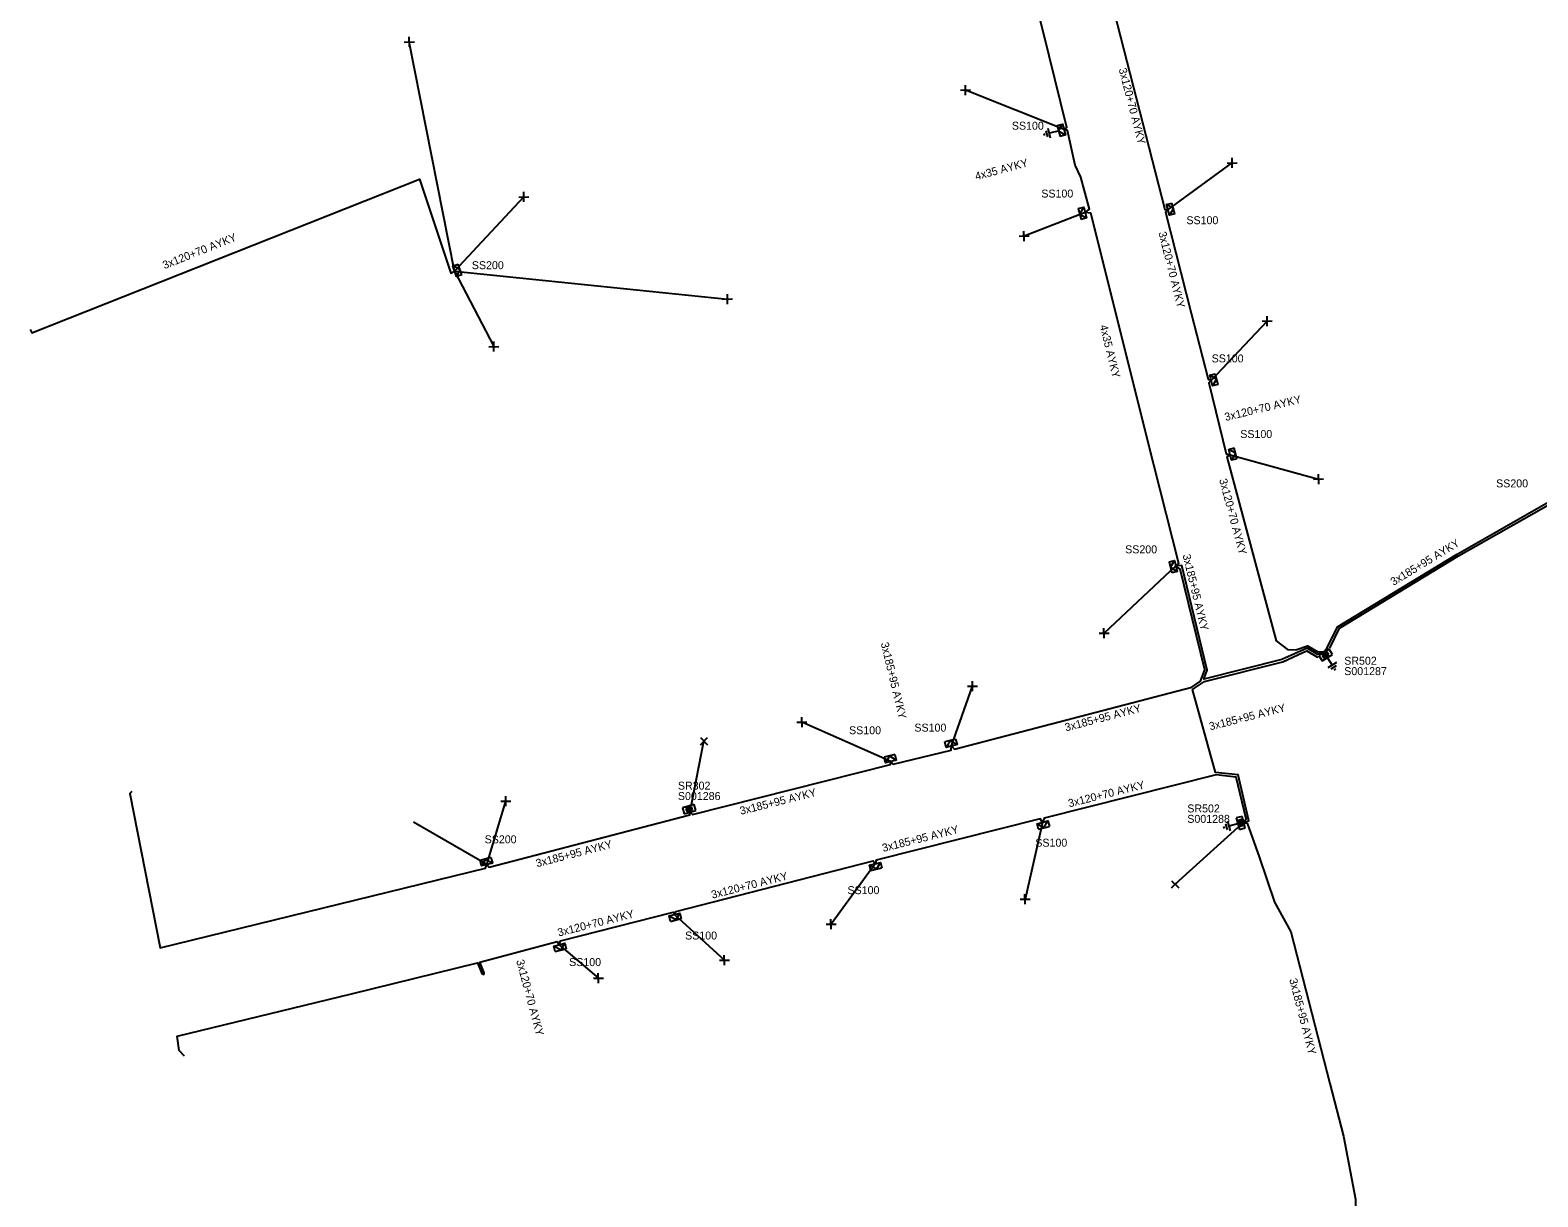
# Model space of a CAD drawing. Extents: x -762500 to -761285, y -1155006 to -1154135.
# Drawn here: x -762396.1 to -762207.7, y -1154854.2 to -1154708.4 of the extents above; entities that cross this region are included whole.
import ezdxf

# ---------------------------------------------------------------- set-up
doc = ezdxf.new("R2010")
doc.units = 0
for name, color, linetype in [('Vrstva 15', 7, 'Continuous'), ('Vrstva 28', 7, 'Continuous'), ('Vrstva 29', 7, 'Continuous'), ('Vrstva 30', 7, 'Continuous'), ('Vrstva 31', 7, 'Continuous'), ('Vrstva 33', 7, 'Continuous'), ('Vrstva 34', 7, 'Continuous'), ('Vrstva 5', 7, 'Continuous'), ('Vrstva 59', 7, 'Continuous'), ('Vrstva 6', 7, 'Continuous')]:
    doc.layers.add(name, color=color, linetype=linetype)

msp = doc.modelspace()

# ---------------------------------------------------------------- linework, layer by layer
at = {"layer": 'Vrstva 15'}
for points in [[(-762269.379, -1154721.432), (-762269.41, -1154721.308)], [(-762269.347, -1154721.561), (-762269.379, -1154721.432)], [(-762268.981, -1154721.729), (-762269.171, -1154720.965)], [(-762268.622, -1154721.888), (-762268.924, -1154720.675)], [(-762267.56, -1154720.979), (-762268.773, -1154721.281)], [(-762234.107, -1154786.711), (-762233.445, -1154787.771)], [(-762232.915, -1154787.44), (-762233.975, -1154788.102)], [(-762232.955, -1154787.83), (-762233.623, -1154788.248)], [(-762233.114, -1154788.301), (-762233.222, -1154788.369)], [(-762233.001, -1154788.23), (-762233.114, -1154788.301)], [(-762246.928, -1154808.035), (-762246.961, -1154807.911)], [(-762246.893, -1154808.163), (-762246.928, -1154808.035)], [(-762246.524, -1154808.324), (-762246.728, -1154807.564)], [(-762246.162, -1154808.477), (-762246.486, -1154807.27)], [(-762245.117, -1154807.55), (-762246.324, -1154807.873)]]:
    msp.add_lwpolyline(points, dxfattribs=at)
at = {"layer": 'Vrstva 28'}
for points in [[(-762233.814, -1154785.768), (-762235.086, -1154786.563)], [(-762234.043, -1154786.127), (-762234.674, -1154786.521)], [(-762234.058, -1154786.192), (-762234.608, -1154786.536)], [(-762234.073, -1154786.257), (-762234.543, -1154786.551)], [(-762234.088, -1154786.322), (-762234.478, -1154786.566)], [(-762234.038, -1154786.402), (-762234.088, -1154786.322)], [(-762233.972, -1154786.417), (-762234.073, -1154786.257)], [(-762233.907, -1154786.432), (-762234.058, -1154786.192)], [(-762233.842, -1154786.447), (-762234.043, -1154786.127)], [(-762233.417, -1154786.404), (-762233.814, -1154785.768)], [(-762235.086, -1154786.563), (-762234.689, -1154787.199)], [(-762234.689, -1154787.199), (-762233.417, -1154786.404)], [(-762234.674, -1154786.521), (-762234.473, -1154786.842)], [(-762234.608, -1154786.536), (-762234.458, -1154786.777)], [(-762234.543, -1154786.551), (-762234.443, -1154786.711)], [(-762234.478, -1154786.566), (-762234.428, -1154786.646)], [(-762234.473, -1154786.842), (-762233.842, -1154786.447)], [(-762234.458, -1154786.777), (-762233.907, -1154786.432)], [(-762234.443, -1154786.711), (-762233.972, -1154786.417)], [(-762234.428, -1154786.646), (-762234.038, -1154786.402)], [(-762234.418, -1154786.584), (-762234.098, -1154786.384)], [(-762313.167, -1154805.186), (-762314.608, -1154805.599)], [(-762314.608, -1154805.599), (-762314.402, -1154806.32)], [(-762314.402, -1154806.32), (-762312.96, -1154805.907)], [(-762313.472, -1154805.47), (-762314.187, -1154805.675)], [(-762314.187, -1154805.675), (-762314.083, -1154806.038)], [(-762313.505, -1154805.528), (-762314.129, -1154805.707)], [(-762314.129, -1154805.707), (-762314.051, -1154805.98)], [(-762314.083, -1154806.038), (-762313.368, -1154805.833)], [(-762313.537, -1154805.587), (-762314.071, -1154805.74)], [(-762314.071, -1154805.74), (-762314.018, -1154805.922)], [(-762314.051, -1154805.98), (-762313.426, -1154805.801)], [(-762314.018, -1154805.922), (-762313.485, -1154805.768)], [(-762313.569, -1154805.645), (-762314.012, -1154805.772)], [(-762314.012, -1154805.772), (-762313.986, -1154805.863)], [(-762313.986, -1154805.863), (-762313.543, -1154805.736)], [(-762313.596, -1154805.702), (-762313.959, -1154805.806)], [(-762313.543, -1154805.736), (-762313.569, -1154805.645)], [(-762313.485, -1154805.768), (-762313.537, -1154805.587)], [(-762313.426, -1154805.801), (-762313.505, -1154805.528)], [(-762313.368, -1154805.833), (-762313.472, -1154805.47)], [(-762312.96, -1154805.907), (-762313.167, -1154805.186)], [(-762244.69, -1154806.657), (-762245.415, -1154806.851)], [(-762245.415, -1154806.851), (-762245.026, -1154808.3)], [(-762244.302, -1154808.105), (-762244.69, -1154806.657)], [(-762244.771, -1154807.063), (-762245.136, -1154807.161)], [(-762245.136, -1154807.161), (-762244.943, -1154807.88)], [(-762244.804, -1154807.121), (-762245.078, -1154807.195)], [(-762245.078, -1154807.195), (-762244.91, -1154807.822)], [(-762245.026, -1154808.3), (-762244.302, -1154808.105)], [(-762244.838, -1154807.179), (-762245.02, -1154807.228)], [(-762245.02, -1154807.228), (-762244.876, -1154807.764)], [(-762244.871, -1154807.237), (-762244.962, -1154807.261)], [(-762244.962, -1154807.261), (-762244.843, -1154807.706)], [(-762244.943, -1154807.88), (-762244.578, -1154807.782)], [(-762244.91, -1154807.822), (-762244.636, -1154807.749)], [(-762244.906, -1154807.289), (-762244.808, -1154807.654)], [(-762244.876, -1154807.764), (-762244.694, -1154807.715)], [(-762244.752, -1154807.682), (-762244.871, -1154807.237)], [(-762244.843, -1154807.706), (-762244.752, -1154807.682)], [(-762244.694, -1154807.715), (-762244.838, -1154807.179)], [(-762244.636, -1154807.749), (-762244.804, -1154807.121)], [(-762244.578, -1154807.782), (-762244.771, -1154807.063)]]:
    msp.add_lwpolyline(points, dxfattribs=at)
at = {"layer": 'Vrstva 31'}
for points in [[(-762267.798, -1154720.323), (-762267.122, -1154720.142), (-762266.76, -1154721.494), (-762267.436, -1154721.675)], [(-762267.798, -1154720.323), (-762267.436, -1154721.675)], [(-762267.617, -1154720.999), (-762267.122, -1154720.142)], [(-762267.617, -1154720.999), (-762266.76, -1154721.494)], [(-762265.159, -1154730.702), (-762264.483, -1154730.521), (-762264.12, -1154731.873), (-762264.797, -1154732.055)], [(-762265.159, -1154730.702), (-762264.797, -1154732.055)], [(-762264.978, -1154731.379), (-762264.483, -1154730.521)], [(-762264.978, -1154731.379), (-762264.12, -1154731.873)], [(-762253.101, -1154731.358), (-762253.777, -1154731.539), (-762254.14, -1154730.186), (-762253.463, -1154730.005)], [(-762253.282, -1154730.681), (-762254.14, -1154730.186)], [(-762253.282, -1154730.681), (-762253.777, -1154731.539)], [(-762253.101, -1154731.358), (-762253.463, -1154730.005)], [(-762342.199, -1154738.957), (-762342.861, -1154739.185), (-762343.317, -1154737.861), (-762342.655, -1154737.633)], [(-762342.427, -1154738.295), (-762343.317, -1154737.861)], [(-762342.427, -1154738.295), (-762342.861, -1154739.185)], [(-762342.199, -1154738.957), (-762342.655, -1154737.633)], [(-762247.702, -1154752.687), (-762248.378, -1154752.868), (-762248.74, -1154751.516), (-762248.064, -1154751.335)], [(-762247.883, -1154752.011), (-762248.74, -1154751.516)], [(-762247.883, -1154752.011), (-762248.378, -1154752.868)], [(-762247.702, -1154752.687), (-762248.064, -1154751.335)], [(-762245.332, -1154761.957), (-762246.008, -1154762.138), (-762246.37, -1154760.786), (-762245.694, -1154760.605)], [(-762245.513, -1154761.281), (-762246.37, -1154760.786)], [(-762245.513, -1154761.281), (-762246.008, -1154762.138)], [(-762245.332, -1154761.957), (-762245.694, -1154760.605)], [(-762253.81, -1154774.847), (-762253.131, -1154774.678), (-762252.792, -1154776.037), (-762253.471, -1154776.206)], [(-762253.81, -1154774.847), (-762253.471, -1154776.206)], [(-762253.641, -1154775.527), (-762253.131, -1154774.678)], [(-762253.641, -1154775.527), (-762252.792, -1154776.037)], [(-762280.492, -1154796.992), (-762281.845, -1154797.354)], [(-762280.492, -1154796.992), (-762280.311, -1154797.668), (-762281.664, -1154798.03), (-762281.845, -1154797.354)], [(-762281.169, -1154797.173), (-762281.664, -1154798.03)], [(-762281.169, -1154797.173), (-762280.311, -1154797.668)], [(-762288.067, -1154798.93), (-762289.426, -1154799.269)], [(-762288.067, -1154798.93), (-762287.898, -1154799.609), (-762289.256, -1154799.948), (-762289.426, -1154799.269)], [(-762288.746, -1154799.099), (-762289.256, -1154799.948)], [(-762288.746, -1154799.099), (-762287.898, -1154799.609)], [(-762270.127, -1154808.268), (-762270.309, -1154807.592), (-762268.956, -1154807.23), (-762268.775, -1154807.906)], [(-762269.451, -1154808.087), (-762270.309, -1154807.592)], [(-762270.127, -1154808.268), (-762268.775, -1154807.906)], [(-762269.451, -1154808.087), (-762268.956, -1154807.23)], [(-762338.552, -1154811.811), (-762339.904, -1154812.174)], [(-762338.552, -1154811.811), (-762338.371, -1154812.488), (-762339.723, -1154812.85), (-762339.904, -1154812.174)], [(-762339.228, -1154811.993), (-762339.723, -1154812.85)], [(-762339.228, -1154811.993), (-762338.371, -1154812.488)], [(-762291.063, -1154813.42), (-762291.232, -1154812.741), (-762289.874, -1154812.402), (-762289.705, -1154813.081)], [(-762290.384, -1154813.251), (-762289.874, -1154812.402)], [(-762290.384, -1154813.251), (-762291.232, -1154812.741)], [(-762291.063, -1154813.42), (-762289.705, -1154813.081)], [(-762316.118, -1154819.778), (-762316.299, -1154819.102), (-762314.947, -1154818.74), (-762314.766, -1154819.416)], [(-762315.442, -1154819.597), (-762316.299, -1154819.102)], [(-762316.118, -1154819.778), (-762314.766, -1154819.416)], [(-762315.442, -1154819.597), (-762314.947, -1154818.74)], [(-762330.507, -1154823.548), (-762330.689, -1154822.872), (-762329.336, -1154822.51), (-762329.155, -1154823.186)], [(-762329.831, -1154823.367), (-762330.689, -1154822.872)], [(-762330.507, -1154823.548), (-762329.155, -1154823.186)], [(-762329.831, -1154823.367), (-762329.336, -1154822.51)]]:
    msp.add_lwpolyline(points, dxfattribs=at)
at = {"layer": 'Vrstva 34'}
for points in [[(-762349.375, -1154709.891), (-762348.125, -1154709.869)], [(-762348.739, -1154710.505), (-762348.761, -1154709.255)], [(-762279.875, -1154715.891), (-762278.625, -1154715.869)], [(-762279.239, -1154716.505), (-762279.261, -1154715.255)], [(-762246.565, -1154725.011), (-762245.315, -1154724.989)], [(-762245.929, -1154725.625), (-762245.951, -1154724.375)], [(-762335.065, -1154729.261), (-762333.815, -1154729.239)], [(-762334.429, -1154729.875), (-762334.451, -1154728.625)], [(-762271.929, -1154734.755), (-762271.951, -1154733.505)], [(-762272.565, -1154734.141), (-762271.315, -1154734.119)], [(-762309.625, -1154742.011), (-762308.375, -1154741.989)], [(-762308.989, -1154742.625), (-762309.011, -1154741.375)], [(-762242.185, -1154744.761), (-762240.935, -1154744.739)], [(-762241.549, -1154745.375), (-762241.571, -1154744.125)], [(-762338.825, -1154747.961), (-762337.575, -1154747.939)], [(-762338.189, -1154748.575), (-762338.211, -1154747.325)], [(-762235.755, -1154764.511), (-762234.505, -1154764.489)], [(-762235.119, -1154765.125), (-762235.141, -1154763.875)], [(-762262.565, -1154783.761), (-762261.315, -1154783.739)], [(-762261.929, -1154784.375), (-762261.951, -1154783.125)], [(-762278.369, -1154791.005), (-762278.391, -1154789.755)], [(-762279.005, -1154790.391), (-762277.755, -1154790.369)], [(-762300.315, -1154794.891), (-762299.065, -1154794.869)], [(-762299.679, -1154795.505), (-762299.701, -1154794.255)], [(-762312.382, -1154796.808), (-762311.498, -1154797.692)], [(-762312.382, -1154797.692), (-762311.498, -1154796.808)], [(-762337.315, -1154804.771), (-762336.065, -1154804.749)], [(-762336.679, -1154805.385), (-762336.701, -1154804.135)], [(-762271.799, -1154817.625), (-762271.821, -1154816.375)], [(-762253.502, -1154814.688), (-762252.618, -1154815.572)], [(-762253.502, -1154815.572), (-762252.618, -1154814.688)], [(-762272.435, -1154817.011), (-762271.185, -1154816.989)], [(-762296.685, -1154820.141), (-762295.435, -1154820.119)], [(-762296.049, -1154820.755), (-762296.071, -1154819.505)], [(-762309.369, -1154825.255), (-762309.391, -1154824.005)], [(-762310.005, -1154824.641), (-762308.755, -1154824.619)], [(-762325.755, -1154826.891), (-762324.505, -1154826.869)], [(-762325.119, -1154827.505), (-762325.141, -1154826.255)]]:
    msp.add_lwpolyline(points, dxfattribs=at)
at = {"layer": 'Vrstva 5'}
for points in [[(-762266.94, -1154720.82), (-762266.61, -1154720.57), (-762269.53, -1154708.55), (-762272.54, -1154696.57), (-762274.83, -1154687.1), (-762275.31, -1154686.99), (-762274.92, -1154686.8), (-762275.94, -1154682.71), (-762267.41, -1154680.81), (-762262.89, -1154698.5), (-762262.21, -1154698.42)], [(-762262.21, -1154698.42), (-762262.53, -1154698.76), (-762261.22, -1154704.16), (-762260.79, -1154704.2), (-762261.11, -1154704.5), (-762254.33, -1154730.82), (-762253.96, -1154730.86), (-762254.25, -1154731.16), (-762251.07, -1154743.75), (-762248.94, -1154752.03), (-762248.56, -1154752.19), (-762248.84, -1154752.46), (-762246.69, -1154761.36), (-762246.19, -1154761.46), (-762246.59, -1154761.73), (-762240.44, -1154784.7), (-762239.02, -1154785.78), (-762237.99, -1154785.84), (-762236.53, -1154785.32), (-762235.21, -1154786.11), (-762234.52, -1154786.06)], [(-762252.96, -1154775.36), (-762252.59, -1154775.07), (-762255.74, -1154762.72), (-762263.59, -1154731.29), (-762264.3, -1154731.2), (-762263.75, -1154730.79), (-762264.83, -1154726.76), (-762265.55, -1154725.29), (-762266.52, -1154720.93), (-762266.94, -1154720.82)], [(-762396.13, -1154745.81), (-762395.92, -1154746.22), (-762347.47, -1154727.01), (-762343.56, -1154738.76), (-762343.09, -1154738.52)], [(-762234.41, -1154785.99), (-762234.08, -1154785.6), (-762232.76, -1154782.95), (-762217.81, -1154773.87), (-762206.44, -1154767.37), (-762206.35, -1154766.69), (-762205.87, -1154767.1), (-762201.48, -1154764.57), (-762197.5, -1154762.89), (-762197.06, -1154762.77), (-762194.48, -1154761.79), (-762190.73, -1154760.6), (-762181.3, -1154758.26), (-762171.71, -1154757.08), (-762165.58, -1154757.01), (-762165.34, -1154756.59)], [(-762233.75, -1154785.62), (-762232.51, -1154783.14), (-762217.64, -1154774.11), (-762206.02, -1154767.5)], [(-762313.58, -1154806.22), (-762313.38, -1154806.4), (-762288.64, -1154800.19), (-762288.58, -1154799.78), (-762288.3, -1154800.11), (-762281.06, -1154798.38), (-762280.99, -1154797.85), (-762280.65, -1154798.27), (-762250.97, -1154790.49), (-762249.88, -1154789.75), (-762249.36, -1154788.36), (-762252.42, -1154775.77), (-762252.96, -1154775.36)], [(-762234.63, -1154786.13), (-762235.24, -1154786.44), (-762236.56, -1154785.65), (-762239.72, -1154787.04), (-762249.47, -1154789.49), (-762249.05, -1154788.38), (-762252.23, -1154775.29), (-762252.96, -1154775.36)], [(-762244.37, -1154807.35), (-762243.84, -1154807.23), (-762245.18, -1154801.48), (-762248, -1154801.17), (-762250.89, -1154790.79), (-762249.41, -1154789.8), (-762239.62, -1154787.32), (-762237.1, -1154786.16), (-762236.59, -1154785.98), (-762235.28, -1154786.77), (-762235.17, -1154786.69)], [(-762244.41, -1154807.22), (-762244.18, -1154806.97), (-762245.42, -1154801.75), (-762247.92, -1154801.46), (-762269.41, -1154806.87), (-762269.63, -1154807.41)], [(-762383.43, -1154803.55), (-762383.69, -1154803.78), (-762379.89, -1154823.06), (-762339.22, -1154813.12), (-762339.05, -1154812.67), (-762338.79, -1154813.01), (-762313.71, -1154806.48), (-762313.71, -1154806.25)], [(-762269.63, -1154807.41), (-762269.91, -1154806.98), (-762290.42, -1154812.13), (-762290.55, -1154812.57)], [(-762244.34, -1154807.48), (-762244.06, -1154807.51), (-762242.57, -1154811.69), (-762240.66, -1154817.36), (-762238.6, -1154821.07), (-762233.72, -1154840.05), (-762232.04, -1154846.62), (-762230.54, -1154854.49), (-762230.71, -1154866.48), (-762226.47, -1154866.4), (-762223.66, -1154866.46), (-762221.96, -1154866.6), (-762221.77, -1154866.8)], [(-762376.84, -1154836.63), (-762377.49, -1154835.9), (-762377.76, -1154834.1), (-762355.96, -1154828.84), (-762340.25, -1154824.96), (-762339.67, -1154826.29), (-762339.46, -1154826.4), (-762339.39, -1154826.19), (-762339.96, -1154824.88), (-762330.28, -1154822.3), (-762330.01, -1154822.69), (-762329.88, -1154822.2), (-762315.77, -1154818.61), (-762315.62, -1154818.92), (-762315.47, -1154818.54), (-762290.79, -1154812.22), (-762290.55, -1154812.57)]]:
    msp.add_lwpolyline(points, dxfattribs=at)
at = {"layer": 'Vrstva 59'}
for points in [[(-762343.09, -1154738.52), (-762348.75, -1154709.88)], [(-762266.94, -1154720.82), (-762279.25, -1154715.88)], [(-762253.96, -1154730.86), (-762245.94, -1154725)], [(-762343.09, -1154738.52), (-762334.44, -1154729.25)], [(-762264.3, -1154731.2), (-762271.94, -1154734.13)], [(-762343.09, -1154738.52), (-762338.2, -1154747.95)], [(-762343.09, -1154738.52), (-762309, -1154742)], [(-762248.56, -1154752.19), (-762241.56, -1154744.75)], [(-762246.19, -1154761.46), (-762235.13, -1154764.5)], [(-762252.96, -1154775.36), (-762261.94, -1154783.75)], [(-762280.99, -1154797.85), (-762278.38, -1154790.38)], [(-762288.58, -1154799.78), (-762299.69, -1154794.88)], [(-762313.49, -1154805.15), (-762311.94, -1154797.25)], [(-762339.05, -1154812.67), (-762336.69, -1154804.76)], [(-762339.05, -1154812.67), (-762348.25, -1154807.38)], [(-762269.63, -1154807.41), (-762271.81, -1154817)], [(-762245.24, -1154808.05), (-762253.06, -1154815.13)], [(-762290.55, -1154812.57), (-762296.06, -1154820.13)], [(-762315.62, -1154818.92), (-762309.38, -1154824.63)], [(-762330.01, -1154822.69), (-762325.13, -1154826.88)]]:
    msp.add_lwpolyline(points, dxfattribs=at)

# ---------------------------------------------------------------- texts
at = {"layer": 'Vrstva 29'}
for s, p in [('S001287', (-762231.93, -1154789)), ('S001286', (-762315.19, -1154804.61)), ('S001288', (-762251.54, -1154807.46))]:
    msp.add_text(s, height=0.9943, dxfattribs=at).set_placement(p)
at = {"layer": 'Vrstva 30'}
for s, p in [('SR502', (-762231.93, -1154787.7)), ('SR302', (-762315.19, -1154803.31)), ('SR502', (-762251.54, -1154806.16))]:
    msp.add_text(s, height=0.9943, dxfattribs=at).set_placement(p)
at = {"layer": 'Vrstva 33'}
for s, p in [('SS100', (-762273.46, -1154720.84)), ('SS100', (-762269.78, -1154729.32)), ('SS100', (-762251.65, -1154732.65)), ('SS200', (-762340.94, -1154738.27)), ('SS100', (-762248.5, -1154749.92)), ('SS100', (-762244.92, -1154759.37)), ('SS200', (-762212.95, -1154765.54)), ('SS200', (-762259.3, -1154773.78)), ('SS100', (-762293.8, -1154796.39)), ('SS100', (-762285.64, -1154796.06)), ('SS200', (-762339.34, -1154810.02)), ('SS100', (-762270.53, -1154810.44)), ('SS100', (-762294, -1154816.37)), ('SS100', (-762314.29, -1154822.04)), ('SS100', (-762328.78, -1154825.36))]:
    msp.add_text(s, height=0.9943, dxfattribs=at).set_placement(p)
at = {"layer": 'Vrstva 6'}
for s, height, rotation, p in [('3x120+70 AYKY', 0.99429, 284.43776, (-762260.12, -1154713.27)), ('4x35 AYKY', 0.9943, 15.02969, (-762277.92, -1154727.16)), ('3x120+70 AYKY', 0.99429, 284.15613, (-762255.16, -1154733.71)), ('3x120+70 AYKY', 0.99429, 21.63198, (-762379.35, -1154738.28)), ('4x35 AYKY', 0.9943, 284.01437, (-762262.5, -1154745.35)), ('3x120+70 AYKY', 0.99428, 13.53101, (-762246.75, -1154757.25)), ('3x120+70 AYKY', 0.99429, 284.99271, (-762247.57, -1154764.58)), ('3x185+95 AYKY', 0.99429, 31.28453, (-762225.78, -1154777.86)), ('3x185+95 AYKY', 0.99429, 283.65869, (-762252.14, -1154774)), ('3x185+95 AYKY', 0.99429, 283.43918, (-762289.85, -1154785.02)), ('3x185+95 AYKY', 0.99429, 14.68929, (-762266.7, -1154796.04)), ('3x185+95 AYKY', 0.99429, 14.19584, (-762248.68, -1154795.91)), ('3x185+95 AYKY', 0.99429, 14.08527, (-762307.32, -1154806.47)), ('3x120+70 AYKY', 0.99429, 14.13844, (-762266.29, -1154805.53)), ('3x185+95 AYKY', 0.99429, 14.07961, (-762289.54, -1154811.1)), ('3x185+95 AYKY', 0.99429, 14.58748, (-762332.8, -1154813.02)), ('3x120+70 AYKY', 0.99429, 14.35308, (-762310.88, -1154816.95)), ('3x120+70 AYKY', 0.99429, 14.24052, (-762330.08, -1154821.67)), ('3x120+70 AYKY', 0.99429, 284.9524, (-762335.4, -1154824.69)), ('3x185+95 AYKY', 0.99429, 284.41916, (-762238.81, -1154827.03))]:
    msp.add_text(s, height=height, rotation=rotation, dxfattribs=at).set_placement(p)

doc.saveas('drawing.dxf')
